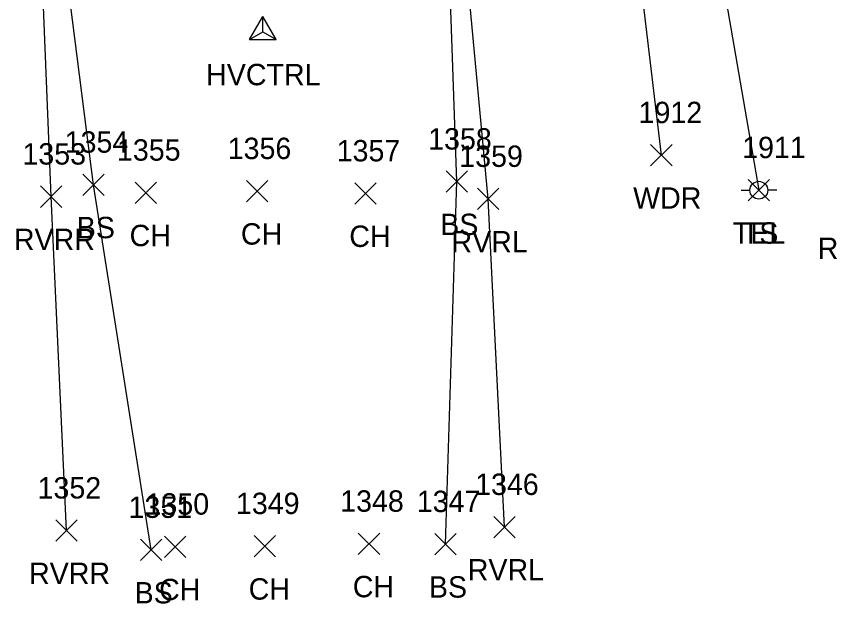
# Model space of a CAD drawing. Extents: x 1600395 to 1603269, y 874955 to 877143.
# Drawn here: x 1601686.9 to 1601763, y 874955 to 875009.9 of the extents above; entities that cross this region are included whole.
import ezdxf

# ---------------------------------------------------------------- set-up
doc = ezdxf.new("R2010")
doc.units = 0
for name, color, linetype in [('C_A', 7, 'Continuous'), ('CPSM', 7, 'Continuous'), ('L_A', 7, 'Continuous'), ('L_I', 7, 'Continuous'), ('L_TIC', 7, 'Continuous'), ('LAWA', 7, 'Continuous'), ('LAWE', 7, 'Continuous'), ('LELB', 7, 'Continuous'), ('P_A', 7, 'Continuous'), ('U_A', 7, 'Continuous'), ('U_I', 7, 'Continuous'), ('UP', 7, 'Continuous')]:
    doc.layers.add(name, color=color, linetype=linetype)

msp = doc.modelspace()

# ---------------------------------------------------------------- linework, layer by layer
at = {"layer": 'CPSM'}
for p, q in [((1601708.741, 875007.761), (1601709.991, 875009.926)), ((1601711.241, 875007.761), (1601709.991, 875009.926)), ((1601709.991, 875008.482), (1601709.991, 875009.926)), ((1601708.741, 875007.761), (1601709.991, 875008.482)), ((1601709.991, 875008.482), (1601709.991, 875008.482)), ((1601709.991, 875008.482), (1601711.241, 875007.761)), ((1601708.741, 875007.761), (1601711.241, 875007.761))]:
    msp.add_line(p, q, dxfattribs=at)
at = {"layer": 'L_TIC'}
for points in [[(1601746.261, 874995.937), (1601748.261, 874997.937)], [(1601748.261, 874995.937), (1601746.261, 874997.937)], [(1601693.142, 874993.174), (1601695.142, 874995.174)], [(1601695.142, 874993.174), (1601693.142, 874995.174)], [(1601727.142, 874993.468), (1601729.142, 874995.468)], [(1601729.142, 874993.468), (1601727.142, 874995.468)], [(1601689.191, 874992.063), (1601691.191, 874994.063)], [(1601691.191, 874992.063), (1601689.191, 874994.063)], [(1601698.036, 874992.43), (1601700.036, 874994.43)], [(1601700.036, 874992.43), (1601698.036, 874994.43)], [(1601708.446, 874992.578), (1601710.446, 874994.578)], [(1601710.446, 874992.578), (1601708.446, 874994.578)], [(1601718.584, 874992.36), (1601720.584, 874994.36)], [(1601720.584, 874992.36), (1601718.584, 874994.36)], [(1601755.383, 874992.664), (1601757.383, 874994.664)], [(1601757.383, 874992.664), (1601755.383, 874994.664)], [(1601730.064, 874991.846), (1601732.064, 874993.846)], [(1601732.064, 874991.846), (1601730.064, 874993.846)], [(1601690.608, 874960.829), (1601692.608, 874962.829)], [(1601692.608, 874960.829), (1601690.608, 874962.829)], [(1601731.591, 874961.163), (1601733.591, 874963.163)], [(1601733.591, 874961.163), (1601731.591, 874963.163)], [(1601700.796, 874959.321), (1601702.796, 874961.321)], [(1601702.796, 874959.321), (1601700.796, 874961.321)], [(1601709.175, 874959.374), (1601711.175, 874961.374)], [(1601711.175, 874959.374), (1601709.175, 874961.374)], [(1601718.915, 874959.594), (1601720.915, 874961.594)], [(1601720.915, 874959.594), (1601718.915, 874961.594)], [(1601726.077, 874959.561), (1601728.077, 874961.561)], [(1601728.077, 874959.561), (1601726.077, 874961.561)], [(1601698.549, 874959.018), (1601700.549, 874961.018)], [(1601700.549, 874959.018), (1601698.549, 874961.018)]]:
    msp.add_lwpolyline(points, dxfattribs=at)
at = {"layer": 'LAWA'}
msp.add_lwpolyline([(1601733.44, 875015.247), (1601735.108, 875042.409), (1601740.466, 875063.57), (1601745.445, 875091.27), (1601756.392, 875091.2), (1601754.181, 875068.768), (1601755.116, 875058.37), (1601744.912, 875016.586), (1601747.261, 874996.937)], dxfattribs=at)
at = {"layer": 'LAWE'}
for points in [[(1601691.608, 874961.829), (1601690.191, 874993.063), (1601689.233, 875017.016), (1601693.176, 875046.242), (1601698.322, 875069.371), (1601704.726, 875096.639), (1601712.321, 875125.386), (1601726.379, 875151.584), (1601742.355, 875184.332), (1601749.838, 875201.821), (1601757.17, 875214.811), (1601763.474, 875228.289), (1601769.619, 875241.931), (1601778.226, 875255.274), (1601780.685, 875261.68), (1601794.383, 875288.119), (1601816.126, 875319.133), (1601836.101, 875339.545), (1601856.898, 875374.373), (1601871.663, 875400.698), (1601886.602, 875430.708)], [(1601732.591, 874962.163), (1601731.064, 874992.846), (1601729.001, 875014.941), (1601729.426, 875043.477), (1601733.933, 875066.276), (1601739.843, 875093.177), (1601757.337, 875121.493)]]:
    msp.add_lwpolyline(points, dxfattribs=at)
at = {"layer": 'LELB'}
for points in [[(1601699.549, 874960.018), (1601694.142, 874994.174), (1601691.323, 875016.49), (1601695.461, 875045.712), (1601700.163, 875068.941), (1601706.127, 875096.094), (1601716.306, 875125.249), (1601727.736, 875151.414), (1601744.118, 875184.771), (1601751.843, 875200.822), (1601755.991, 875200.418)], [(1601727.077, 874960.561), (1601728.142, 874994.468), (1601727.416, 875015.008), (1601727.587, 875043.323), (1601731.608, 875066.074), (1601737.893, 875093.047), (1601755.131, 875122.883), (1601766.475, 875138.812), (1601780.415, 875159.083), (1601801.249, 875183.04), (1601811.363, 875189.98)], [(1601765.681, 875088.224), (1601759.882, 875066.311), (1601757.66, 875057.618), (1601751.312, 875023.094), (1601756.383, 874993.664)]]:
    msp.add_lwpolyline(points, dxfattribs=at)
at = {"layer": 'UP'}
for p, q in [((1601754.724, 874993.659), (1601755.55, 874993.659)), ((1601756.383, 874993.664), (1601756.383, 874993.664)), ((1601758.05, 874993.664), (1601757.216, 874993.664)), ((1601757.216, 874993.664), (1601757.216, 874993.664)), ((1601758.05, 874993.664), (1601758.05, 874993.664))]:
    msp.add_line(p, q, dxfattribs=at)
msp.add_circle((1601756.383, 874993.664), 0.833, dxfattribs=at)

# ---------------------------------------------------------------- texts
at = {"layer": 'C_A'}
msp.add_text('HVCTRL', height=2, dxfattribs=at).set_placement((1601704.684, 875003.482))
at = {"layer": 'L_A'}
for s, p in [('WDR', (1601744.623, 874991.937)), ('BS', (1601692.583, 874989.174)), ('BS', (1601726.583, 874989.468)), ('CH', (1601697.524, 874988.43)), ('CH', (1601707.934, 874988.578)), ('CH', (1601718.073, 874988.36)), ('TS', (1601754.792, 874988.664)), ('RVRR', (1601686.703, 874988.063)), ('RVRL', (1601727.63, 874987.846)), ('RVRL', (1601729.157, 874957.163)), ('RVRR', (1601688.12, 874956.829)), ('CH', (1601718.403, 874955.594)), ('BS', (1601725.518, 874955.561)), ('BS', (1601697.99, 874955.018)), ('CH', (1601700.284, 874955.321)), ('CH', (1601708.663, 874955.374))]:
    msp.add_text(s, height=2, dxfattribs=at).set_placement(p)
at = {"layer": 'L_I'}
for s, p in [('1912', (1601745.135, 874999.937)), ('1358', (1601725.45, 874997.468)), ('1354', (1601691.45, 874997.174)), ('1356', (1601706.698, 874996.578)), ('1911', (1601754.824, 874996.664)), ('1353', (1601687.498, 874996.063)), ('1355', (1601696.343, 874996.43)), ('1357', (1601716.892, 874996.36)), ('1359', (1601728.363, 874995.846)), ('1352', (1601688.915, 874964.829)), ('1346', (1601729.843, 874965.163)), ('1350', (1601699.016, 874963.321)), ('1349', (1601707.474, 874963.374)), ('1348', (1601717.222, 874963.594)), ('1347', (1601724.385, 874963.561)), ('1351', (1601697.424, 874963.018))]:
    msp.add_text(s, height=2, dxfattribs=at).set_placement(p)
at = {"layer": 'P_A'}
msp.add_text('RDP', height=2, dxfattribs=at).set_placement((1601761.888, 874987.239))
at = {"layer": 'U_A'}
msp.add_text('TEL', height=2, dxfattribs=at).set_placement((1601753.942, 874988.664))
at = {"layer": 'U_I'}
msp.add_text('1911', height=2, dxfattribs=at).set_placement((1601754.824, 874996.664))

doc.saveas('drawing.dxf')
